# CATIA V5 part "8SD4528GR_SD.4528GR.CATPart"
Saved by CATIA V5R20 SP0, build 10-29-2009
Part number: 8SD4528GR_SD.4528GR
Revision: ANY
Definition: UNKNOWN
Nomenclature: 8SD4528GR_SD.4528GR
Source: Unknown
Bounding box of the stored display mesh (mm): x -22.5 to 22.5, y -22 to 22, z -14 to 14
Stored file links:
  C:\Users\Utente\Desktop\IO LAVORO\3D X SITO CF\CUMSA\3D files SD\SD 4528\8SD4528GR_SD.4528GR.CATPart
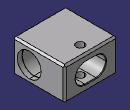
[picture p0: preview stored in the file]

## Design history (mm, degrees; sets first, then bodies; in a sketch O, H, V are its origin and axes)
Body1 "Chaflán3" (main body)
  Solid1: solid without history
